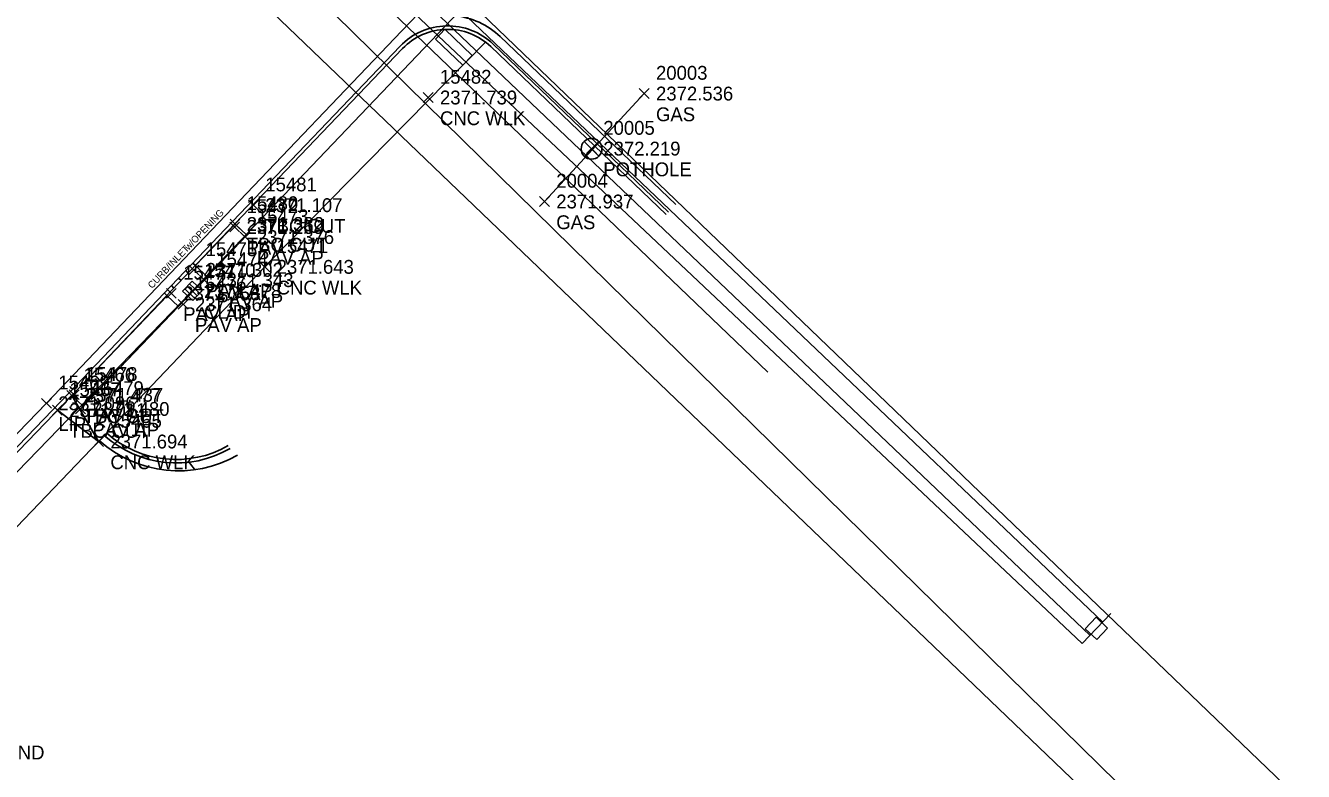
# Model space of a CAD drawing. Extents: x 2377639 to 2379738, y 729875 to 732734.
# Drawn here: x 2378926.7 to 2379111.4, y 731060.9 to 731168.7 of the extents above; entities that cross this region are included whole.
import ezdxf

# ---------------------------------------------------------------- set-up
doc = ezdxf.new("R2010")
doc.units = 0
for name, color, linetype in [('Default', 7, 'Continuous'), ('TOPO_CURBGTR_Back-of-Curb', 7, 'Continuous'), ('TOPO_CURBGTR_Face-of-Curb', 7, 'Continuous'), ('TOPO_CURBGTR_Lip-of-Gutter', 7, 'Continuous'), ('TOPO_DATA_Elevations', 7, 'Continuous'), ('TOPO_DATA_Notes', 7, 'Continuous'), ('TOPO_ELEC_Cable_Overhead-Exist', 7, 'Continuous'), ('TOPO_ELEC_Power-Pole', 7, 'Continuous'), ('TOPO_GAS_Line', 7, 'Continuous'), ('TOPO_GEOLOGY_Test-Hole', 7, 'Continuous'), ('TOPO_MISC_Flat-Asphalt', 7, 'Continuous'), ('TOPO_SAN_Plastic-Pipe', 7, 'Continuous'), ('TOPO_STORM_Inlet', 7, 'Continuous'), ('TOPO_STORM_Line-Other', 7, 'Continuous'), ('TOPO_SW_Back', 7, 'Continuous'), ('TOPO_TELE_Overhead-Line', 7, 'Continuous'), ('TOPO_TELE_Underground-FO-Cable', 7, 'Continuous'), ('TOPO_TV_Cable-Overhead', 7, 'Continuous')]:
    doc.layers.add(name, color=color, linetype=linetype)

# ---------------------------------------------------------------- blocks, each defined once
blk = doc.blocks.new('DI_7')
at = {"layer": 'Default'}
for p, q in [((0, 0.0121), (0.0254, 0.0121)), ((0, -0.0133), (0, 0.0121)), ((0.0254, 0.0064), (0, 0.0064)), ((0.0254, 0), (0, 0)), ((0.0254, 0.0121), (0.0254, -0.0133)), ((0.0254, -0.0064), (0, -0.0064)), ((0.0254, -0.0133), (0, -0.0133))]:
    blk.add_line(p, q, dxfattribs=at)
blk = doc.blocks.new('BORE_1')
at = {"layer": 'Default'}
for p, q in [((-0.135, 0.129), (0.135, -0.139)), ((0.137, 0.13), (-0.13, -0.142))]:
    blk.add_line(p, q, dxfattribs=at)
blk.add_circle((0.001, -0.003), 0.191, dxfattribs=at)
blk = doc.blocks.new('UP_1')
at = {"layer": 'Default'}
for p, q in [((0, 0.0381), (0, -0.0381)), ((-0.0145, 0.0145), (0.0145, 0.0145)), ((-0.0145, -0.0145), (-0.0145, 0.0145)), ((0.0145, 0.0145), (0.0145, -0.0145)), ((0.0145, -0.0145), (-0.0145, -0.0145))]:
    blk.add_line(p, q, dxfattribs=at)

msp = doc.modelspace()

# ---------------------------------------------------------------- linework, layer by layer
at = {"layer": 'TOPO_CURBGTR_Back-of-Curb'}
msp.add_line((2378993.92, 731165.7), (2379019.27, 731141.41), dxfattribs=at)
for points in [[(2378956.9, 731140.01), (2378956.94, 731140.05), (2378981.18, 731165.42)], [(2378885.04, 731064.89), (2378888.91, 731069.01), (2378903.95, 731084.78), (2378933.36, 731115.26), (2378956.9, 731140.01)]]:
    msp.add_lwpolyline(points, dxfattribs=at)
for centre, radius, start, end in [((2378987.69, 731159.2), 9, 46.2211, 136.3064), ((2378948.45, 731121.12), 15.13, 228.3898, 299.8447)]:
    msp.add_arc(centre, radius, start, end, dxfattribs=at)
at = {"layer": 'TOPO_CURBGTR_Face-of-Curb'}
msp.add_line((2378994.26, 731166.06), (2379019.62, 731141.77), dxfattribs=at)
for points in [[(2378956.54, 731140.36), (2378956.58, 731140.39), (2378980.82, 731165.77)], [(2378884.69, 731065.24), (2378888.55, 731069.36), (2378903.59, 731085.13), (2378933, 731115.61), (2378956.54, 731140.36)]]:
    msp.add_lwpolyline(points, dxfattribs=at)
for centre, radius, start, end in [((2378987.69, 731159.2), 9.5, 46.2211, 136.3064), ((2378948.45, 731121.12), 15.63, 228.3273, 299.8447)]:
    msp.add_arc(centre, radius, start, end, dxfattribs=at)
at = {"layer": 'TOPO_CURBGTR_Lip-of-Gutter'}
for p, q in [((2378981.07, 731167.99), (2379018.48, 731207.18)), ((2378955.59, 731141.27), (2378981.07, 731167.99)), ((2378995.3, 731167.15), (2379020.65, 731142.85))]:
    msp.add_line(p, q, dxfattribs=at)
msp.add_lwpolyline([(2378882.44, 731064.55), (2378887.47, 731070.48), (2378929.7, 731114.12), (2378955.59, 731141.27)], dxfattribs=at)
for centre, radius, start, end in [((2378987.69, 731159.2), 11, 46.2211, 84.8948), ((2378948.78, 731121.47), 17.13, 228.157, 299.8447)]:
    msp.add_arc(centre, radius, start, end, dxfattribs=at)
at = {"layer": 'TOPO_DATA_Elevations'}
for p, q in [((2378984.16, 731157.64), (2378985.58, 731159.05)), ((2378984.16, 731159.05), (2378985.58, 731157.64)), ((2379015.39, 731158.2), (2379016.81, 731159.62)), ((2379015.39, 731159.62), (2379016.81, 731158.2)), ((2379007.77, 731150.25), (2379009.19, 731151.66)), ((2379007.77, 731151.66), (2379009.19, 731150.25)), ((2379000.98, 731142.59), (2379002.39, 731144.01)), ((2379000.98, 731144.01), (2379002.39, 731142.59)), ((2378958.91, 731142.06), (2378960.33, 731143.48)), ((2378958.91, 731143.48), (2378960.33, 731142.06)), ((2378956.2, 731138.91), (2378957.62, 731140.33)), ((2378956.2, 731140.33), (2378957.62, 731138.91)), ((2378956.23, 731139.34), (2378957.65, 731140.75)), ((2378956.23, 731140.75), (2378957.65, 731139.34)), ((2378957.71, 731137.46), (2378959.12, 731138.87)), ((2378957.71, 731138.87), (2378959.12, 731137.46)), ((2378960.55, 731133.14), (2378961.97, 731134.55)), ((2378960.55, 731134.55), (2378961.97, 731133.14)), ((2378950.29, 731132.7), (2378951.71, 731134.11)), ((2378950.29, 731134.11), (2378951.71, 731132.7)), ((2378951.83, 731131.22), (2378953.25, 731132.64)), ((2378951.83, 731132.64), (2378953.25, 731131.22)), ((2378947.04, 731129.32), (2378948.46, 731130.73)), ((2378947.04, 731130.73), (2378948.46, 731129.32)), ((2378950.06, 731129.64), (2378951.48, 731131.06)), ((2378950.06, 731131.06), (2378951.48, 731129.64)), ((2378948.75, 731127.73), (2378950.16, 731129.15)), ((2378948.75, 731129.15), (2378950.16, 731127.73)), ((2378932.66, 731114.55), (2378934.07, 731115.97)), ((2378932.66, 731115.97), (2378934.07, 731114.55)), ((2378932.99, 731114.65), (2378934.41, 731116.06)), ((2378932.99, 731116.06), (2378934.41, 731114.65)), ((2378928.99, 731113.42), (2378930.41, 731114.83)), ((2378928.99, 731114.83), (2378930.41, 731113.42)), ((2378930.57, 731112.42), (2378931.99, 731113.83)), ((2378930.57, 731113.83), (2378931.99, 731112.42)), ((2378933.91, 731112.6), (2378935.33, 731114.01)), ((2378933.91, 731114.01), (2378935.33, 731112.6)), ((2378936.53, 731107.88), (2378937.94, 731109.29)), ((2378936.53, 731109.29), (2378937.94, 731107.88))]:
    msp.add_line(p, q, dxfattribs=at)
at = {"layer": 'TOPO_ELEC_Cable_Overhead-Exist'}
for p, q in [((2379082.38, 731082.46), (2378871.59, 731283.35)), ((2379080.54, 731080.57), (2378869.76, 731281.46))]:
    msp.add_line(p, q, dxfattribs=at)
at = {"layer": 'TOPO_GAS_Line'}
for p, q in [((2378817.91, 731309.25), (2379078.96, 731058.81)), ((2379001.69, 731143.3), (2379016.1, 731158.91))]:
    msp.add_line(p, q, dxfattribs=at)
at = {"layer": 'TOPO_MISC_Flat-Asphalt'}
for points in [[(2378951.23, 731134.05), (2378956.96, 731140.03), (2378958.65, 731138.41), (2378952.93, 731132.43)], [(2378933.36, 731115.26), (2378947.15, 731129.66), (2378948.78, 731128.1), (2378935, 731113.7)]]:
    msp.add_lwpolyline(points, close=True, dxfattribs=at)
at = {"layer": 'TOPO_SAN_Plastic-Pipe'}
msp.add_line((2379189.26, 730956.35), (2378923.42, 731217.48), dxfattribs=at)
at = {"layer": 'TOPO_STORM_Inlet'}
for p, q in [((2378951.23, 731134.05), (2378950.87, 731134.39)), ((2378949.84, 731133.3), (2378950.2, 731132.96)), ((2378947.77, 731131.13), (2378948.13, 731130.79)), ((2378948.8, 731132.22), (2378949.17, 731131.87)), ((2378947.1, 731129.7), (2378946.74, 731130.04))]:
    msp.add_line(p, q, dxfattribs=at)
at = {"layer": 'TOPO_STORM_Line-Other'}
for p, q in [((2379116.84, 731304.52), (2378950.77, 731130.35)), ((2378950.77, 731130.35), (2378841.19, 731017.26))]:
    msp.add_line(p, q, dxfattribs=at)
at = {"layer": 'TOPO_SW_Back'}
for p, q in [((2378962.25, 731134.88), (2378993.16, 731166.35)), ((2378934.54, 731113.22), (2378958.61, 731138.37)), ((2378952.93, 731132.43), (2378951.23, 731134.05)), ((2378948.78, 731128.1), (2378947.1, 731129.7))]:
    msp.add_line(p, q, dxfattribs=at)
msp.add_lwpolyline([(2378985.94, 731166.78), (2378989.88, 731163.01), (2378991.25, 731164.4), (2378987.3, 731168.2)], close=True, dxfattribs=at)
for points in [[(2378901.48, 731051.09), (2378893.74, 731059.81), (2378894.32, 731063.89), (2378899.02, 731068.85), (2378911.41, 731081.67), (2378937.23, 731108.59), (2378961.26, 731133.85), (2378962.25, 731134.88)], [(2378931.3, 731113.12), (2378937.23, 731108.59), (2378933.36, 731115.26)]]:
    msp.add_lwpolyline(points, dxfattribs=at)
at = {"layer": 'TOPO_TELE_Overhead-Line'}
msp.add_line((2379079.4, 731079.39), (2378867.97, 731279.01), dxfattribs=at)
at = {"layer": 'TOPO_TELE_Underground-FO-Cable'}
msp.add_line((2379033.97, 731118.6), (2378867.09, 731278.7), dxfattribs=at)
at = {"layer": 'TOPO_TV_Cable-Overhead'}
msp.add_line((2379199.34, 730971.87), (2378747.39, 731406.04), dxfattribs=at)

# ---------------------------------------------------------------- block references
at = {"layer": 'TOPO_ELEC_Power-Pole', "xscale": 78.74000000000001, "yscale": 78.74, "rotation": -43.76602493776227}
msp.add_blockref('UP_1', (2379081.48, 731081.56), dxfattribs=at)
at = {"layer": 'TOPO_GEOLOGY_Test-Hole', "xscale": 7.8740000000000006, "yscale": 7.8740000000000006}
msp.add_blockref('BORE_1', (2379008.48, 731150.95), dxfattribs=at)
at = {"layer": 'TOPO_STORM_Inlet', "xscale": 78.74, "yscale": 78.74, "rotation": 136.4356482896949}
msp.add_blockref('DI_7', (2378951.49, 731129.66), dxfattribs=at)

# ---------------------------------------------------------------- texts
at = {"layer": 'TOPO_DATA_Elevations'}
for s, p in [('15482', (2378986.58, 731160.34)), ('20003', (2379017.81, 731160.91)), ('2371.739', (2378986.58, 731157.34)), ('2372.536', (2379017.81, 731157.91)), ('GAS', (2379017.81, 731154.91)), ('CNC WLK', (2378986.58, 731154.34)), ('20005', (2379010.19, 731152.95)), ('2372.219', (2379010.19, 731149.95)), ('20004', (2379003.39, 731145.3)), ('POTHOLE', (2379010.19, 731146.95)), ('15481', (2378961.33, 731144.77)), ('15472', (2378958.62, 731141.62)), ('15480', (2378958.65, 731142.05)), ('2371.107', (2378961.33, 731141.77)), ('2371.937', (2379003.39, 731142.3)), ('15473', (2378960.12, 731140.16)), ('2371.269', (2378958.62, 731138.62)), ('2371.382', (2378958.65, 731139.05)), ('TBC CUT', (2378961.33, 731138.77)), ('GAS', (2379003.39, 731139.3)), ('TBC CUT', (2378958.65, 731136.05)), ('2371.376', (2378960.12, 731137.16)), ('15475', (2378952.71, 731135.41)), ('PAV', (2378958.62, 731135.62)), ('15471', (2378962.97, 731135.85)), ('15470', (2378952.48, 731132.35)), ('2371.302', (2378952.71, 731132.41)), ('15474', (2378954.25, 731133.93)), ('PAV AP', (2378960.12, 731134.16)), ('2371.643', (2378962.97, 731132.85)), ('15477', (2378949.46, 731132.02)), ('2371.343', (2378954.25, 731130.93)), ('2371.353', (2378949.46, 731129.02)), ('15476', (2378951.16, 731130.44)), ('2371.478', (2378952.48, 731129.35)), ('PAV AP', (2378952.71, 731129.41)), ('CNC WLK', (2378962.97, 731129.85)), ('2371.364', (2378951.16, 731127.44)), ('PAV AP', (2378954.25, 731127.93)), ('PAV AP', (2378949.46, 731126.02)), ('CL DI', (2378952.48, 731126.35)), ('PAV AP', (2378951.16, 731124.44)), ('15469', (2378931.41, 731116.12)), ('15466', (2378935.07, 731117.26)), ('15478', (2378935.41, 731117.35)), ('15467', (2378932.99, 731115.13)), ('2371.477', (2378935.07, 731114.26)), ('2371.437', (2378935.41, 731114.35)), ('15479', (2378936.33, 731115.3)), ('2371.096', (2378931.41, 731113.12)), ('2371.011', (2378932.99, 731112.13)), ('2371.480', (2378936.33, 731112.3)), ('TBC CUT', (2378935.07, 731111.26)), ('PAV AP', (2378935.41, 731111.35)), ('15465', (2378938.94, 731110.59)), ('LIP', (2378931.41, 731110.12)), ('TBC CUT', (2378932.99, 731109.13)), ('PAV AP', (2378936.33, 731109.3)), ('2371.694', (2378938.94, 731107.59)), ('CNC WLK', (2378938.94, 731104.59)), ('EB CL 7 END', (2378913.06, 731062.62))]:
    msp.add_text(s, height=2, dxfattribs=at).set_placement(p)
at = {"layer": 'TOPO_DATA_Notes'}
for s, p in [('w/OPENING', (2378950.26, 731136.18)), ('CURB/INLET', (2378944.95, 731130.63))]:
    msp.add_text(s, height=1, rotation=46.4356, dxfattribs=at).set_placement(p)

doc.saveas('drawing.dxf')
